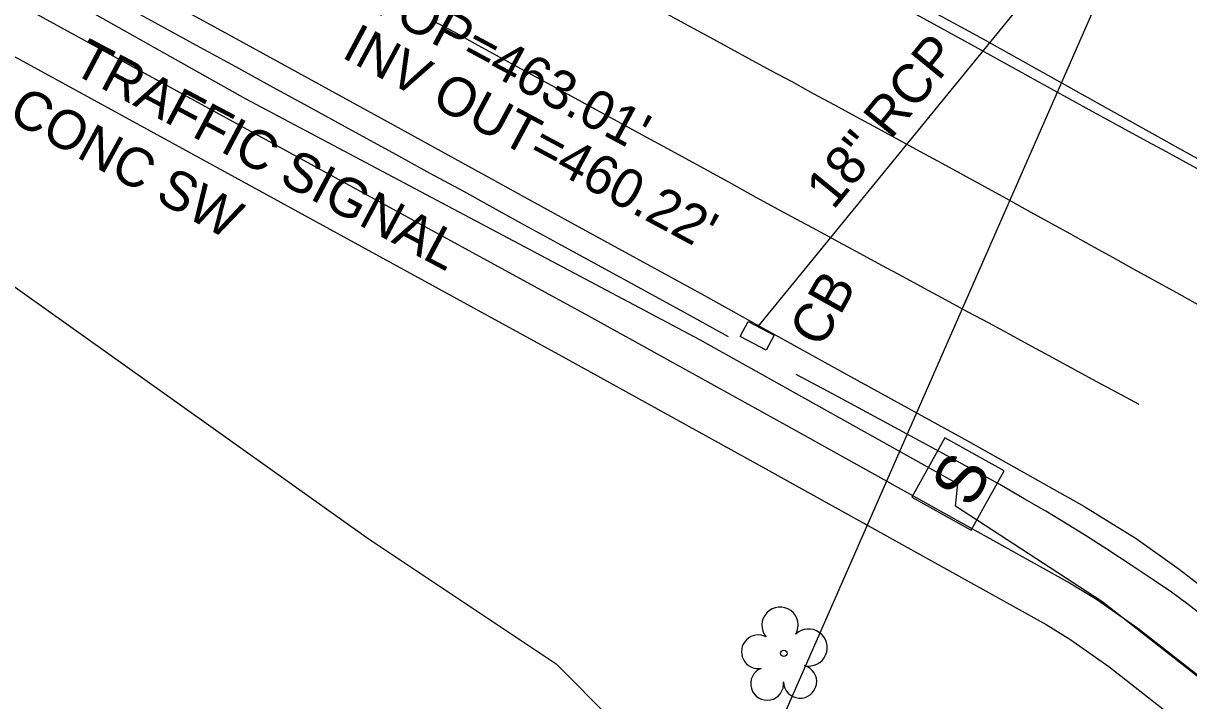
# Model space of a CAD drawing. Extents: x 2074109 to 2077820, y 741079 to 746031.
# Drawn here: x 2074923.4 to 2075042.9, y 743570.1 to 743639.5 of the extents above; entities that cross this region are included whole.
import ezdxf

# ---------------------------------------------------------------- set-up
doc = ezdxf.new("R2010")
doc.units = 0
for name, color, linetype in [('Exist Roads Curbs', 7, 'Continuous'), ('Exist Roads EOP', 7, 'Continuous'), ('Exist Roads EOP Other', 7, 'Continuous'), ('Exist Roads EOP Other Text', 7, 'Continuous'), ('Exist Roads EOT', 7, 'Continuous'), ('Exist Structure Minor Catch Basin', 7, 'Continuous'), ('Exist Structure Minor Catch Basin Text', 7, 'Continuous'), ('Exist Structure Minor Drop Inlet Top Elevation', 7, 'Continuous'), ('Exist Structure Minor Pipes RCP 18 Inch', 7, 'Continuous'), ('Exist Structure Minor Pipes RCP 18 Inch Invert', 7, 'Continuous'), ('Exist Structure Minor Pipes RCP 18 Inch Text', 7, 'Continuous'), ('Exist Structure Minor Pipes RCP 54 Inch', 7, 'Continuous'), ('Exist Utilities Other Traffic Signal Box CELL', 7, 'Continuous'), ('Exist Utilities Power UG Cable SUE LOS B', 7, 'Continuous'), ('Exist Utilities Power UG Cable SUE LOS B Text', 7, 'Continuous'), ('Exist Vegetation Tree CELL', 7, 'Continuous'), ('Exist Vegetation Woods Line', 7, 'Continuous')]:
    doc.layers.add(name, color=color, linetype=linetype)

msp = doc.modelspace()

# ---------------------------------------------------------------- linework, layer by layer
at = {"layer": 'Exist Roads Curbs'}
for points in [[(2074917.19, 743694.96), (2074926.95, 743689.34), (2074936.83, 743683.8), (2074947.07, 743678.19), (2074957.61, 743672.52), (2074968.41, 743666.75), (2074979.41, 743660.86), (2074990.43, 743654.92), (2075001.15, 743649.16), (2075011.47, 743643.59), (2075021.55, 743638.07), (2075031.64, 743632.44), (2075042.15, 743626.6), (2075053.19, 743620.49)], [(2074922.21, 743647.6), (2074925.14, 743646), (2074928.17, 743644.36), (2074931.3, 743642.65), (2074934.56, 743640.88), (2074937.96, 743639.03), (2074941.49, 743637.1), (2074945.16, 743635.09), (2074948.98, 743633), (2074952.95, 743630.83), (2074957.06, 743628.58), (2074961.25, 743626.29), (2074965.1, 743624.18), (2074968.53, 743622.31), (2074971.54, 743620.65), (2074974.39, 743619.09), (2074978.53, 743616.82), (2074984.23, 743613.7), (2074991.47, 743609.74), (2074995.67, 743607.44)], [(2075056.02, 743568.57), (2075054.3, 743570.23), (2075052.3, 743572.09), (2075050.06, 743574.09), (2075047.65, 743576.14), (2075045.13, 743578.18), (2075042.84, 743579.95), (2075041.13, 743581.22), (2075039.38, 743582.42), (2075037.01, 743584), (2075034.5, 743585.64), (2075032.31, 743587.04), (2075030.29, 743588.3), (2075028.25, 743589.51), (2075026.05, 743590.78), (2075023.53, 743592.24), (2075016.96, 743595.84), (2075006.96, 743601.23), (2075002.65, 743603.54)]]:
    msp.add_lwpolyline(points, dxfattribs=at)
at = {"layer": 'Exist Roads EOP'}
for points in [[(2074922.82, 743690.67), (2074926.1, 743688.81), (2074931.43, 743685.89), (2074937.13, 743682.79), (2074941.49, 743680.41), (2074946.08, 743677.9), (2074952.54, 743674.38), (2074960.81, 743669.87), (2074970.75, 743664.43), (2074980.82, 743658.94), (2074989.54, 743654.21), (2074997.67, 743649.82), (2075005.98, 743645.32), (2075013.05, 743641.48), (2075017.5, 743639.06), (2075021.29, 743636.97), (2075026.41, 743634.14), (2075032.37, 743630.86), (2075038.62, 743627.45), (2075040.22, 743626.58), (2075046.82, 743622.98)], [(2074913.35, 743655.38), (2074929.24, 743646.71), (2074944.83, 743638.18), (2074961.47, 743629.04), (2074979.24, 743619.29), (2074993.27, 743611.63), (2074999.52, 743608.13), (2075007.53, 743603.69), (2075020.31, 743596.69), (2075032.14, 743590.05), (2075037.51, 743586.73), (2075041.93, 743583.59), (2075046.53, 743580.01), (2075052.2, 743575.32), (2075057.95, 743570.11), (2075063.14, 743564.87)]]:
    msp.add_lwpolyline(points, dxfattribs=at)
at = {"layer": 'Exist Roads EOP Other'}
for points in [[(2074736.15, 743743.52), (2074745.36, 743738.39), (2074764.63, 743727.87), (2074783.88, 743717.41), (2074799.06, 743709.14), (2074820.47, 743697.56), (2074844.02, 743684.7), (2074871.78, 743669.61), (2074897.44, 743655.45), (2074932.64, 743636.17), (2074957.19, 743622.75), (2074981.37, 743609.53), (2075002.24, 743597.98), (2075030.68, 743582.18), (2075033.44, 743580.49), (2075037.68, 743577.54), (2075043.96, 743572.63), (2075050.45, 743567.5), (2075053.78, 743564.46), (2075055.44, 743566.25), (2075056.43, 743567.41)], [(2074733.88, 743739.15), (2074742.99, 743734.08), (2074762.28, 743723.55), (2074781.53, 743713.09), (2074796.71, 743704.81), (2074818.12, 743693.23), (2074841.67, 743680.38), (2074869.42, 743665.29), (2074895.07, 743651.14), (2074930.28, 743631.85), (2074954.82, 743618.43), (2074979, 743605.22), (2074999.86, 743593.68), (2075028.28, 743577.89), (2075030.72, 743576.39), (2075034.73, 743573.6), (2075040.92, 743568.76), (2075047.31, 743563.7), (2075054.69, 743557.36), (2075060.75, 743551.55), (2075061.79, 743551.62), (2075067.53, 743555.92)]]:
    msp.add_lwpolyline(points, dxfattribs=at)
at = {"layer": 'Exist Roads EOT'}
for points in [[(2074989.02, 743640.71), (2074991.22, 743639.52), (2074993.41, 743638.32), (2074995.61, 743637.13), (2074997.81, 743635.94), (2075000, 743634.74), (2075002.2, 743633.55), (2075004.39, 743632.35), (2075006.59, 743631.16), (2075008.79, 743629.97), (2075010.98, 743628.77), (2075013.18, 743627.59), (2075015.38, 743626.4), (2075017.58, 743625.21), (2075019.77, 743624.01), (2075021.96, 743622.8), (2075024.15, 743621.59), (2075026.34, 743620.38), (2075028.52, 743619.18), (2075030.71, 743617.97), (2075032.9, 743616.76), (2075035.09, 743615.55), (2075037.28, 743614.34), (2075039.46, 743613.13), (2075041.65, 743611.93), (2075043.84, 743610.72)], [(2075037.82, 743600.45), (2075035.62, 743601.64), (2075033.42, 743602.83), (2075031.23, 743604.02), (2075029.03, 743605.21), (2075026.83, 743606.4), (2075024.63, 743607.59), (2075022.43, 743608.78), (2075020.23, 743609.96), (2075018.03, 743611.15), (2075015.83, 743612.34), (2075013.64, 743613.53), (2075011.44, 743614.72), (2075009.24, 743615.91), (2075007.04, 743617.09), (2075004.84, 743618.28), (2075002.64, 743619.47), (2075000.44, 743620.66), (2074998.25, 743621.86), (2074996.06, 743623.06), (2074993.86, 743624.26), (2074991.67, 743625.46), (2074989.48, 743626.65), (2074987.28, 743627.85), (2074985.09, 743629.05), (2074982.89, 743630.25), (2074980.7, 743631.45), (2074978.51, 743632.65), (2074976.31, 743633.84), (2074974.12, 743635.04), (2074971.93, 743636.24), (2074969.73, 743637.44), (2074967.54, 743638.64), (2074965.34, 743639.83)]]:
    msp.add_lwpolyline(points, dxfattribs=at)
at = {"layer": 'Exist Structure Minor Catch Basin'}
msp.add_lwpolyline([(2074999.58, 743606.01), (2074996.9, 743607.44), (2074997.73, 743608.98), (2075000.41, 743607.55)], close=True, dxfattribs=at)
at = {"layer": 'Exist Structure Minor Pipes RCP 18 Inch'}
msp.add_line((2074998.76, 743608.45), (2075047.69, 743668.37), dxfattribs=at)
at = {"layer": 'Exist Structure Minor Pipes RCP 54 Inch'}
msp.add_line((2075074.8, 743735.81), (2074946.91, 743444.52), dxfattribs=at)
at = {"layer": 'Exist Utilities Other Traffic Signal Box CELL'}
msp.add_line((2075019.25, 743592.31), (2075019.25, 743592.31), dxfattribs=at)
msp.add_lwpolyline([(2075020.61, 743587.59), (2075023.97, 743593.67), (2075017.89, 743597.03), (2075014.53, 743590.95), (2075020.61, 743587.59)], dxfattribs=at)
at = {"layer": 'Exist Utilities Power UG Cable SUE LOS B'}
for points in [[(2074807.97, 743711.12), (2074807.03, 743709.66), (2074864.42, 743676.69), (2074899.54, 743658.03), (2074946.14, 743631.83), (2074992.75, 743607.11), (2075019.25, 743592.31)], [(2075056.41, 743555.92), (2075056.18, 743560.57), (2075053.43, 743565.07), (2075034.01, 743580.27), (2075019.01, 743590.04), (2075019.25, 743592.31)]]:
    msp.add_lwpolyline(points, dxfattribs=at)
at = {"layer": 'Exist Vegetation Tree CELL'}
msp.add_line((2075001.39, 743574.95), (2075001.39, 743574.95), dxfattribs=at)
msp.add_circle((2075001.39, 743574.95), 0.326, dxfattribs=at)
for centre, radius, start, end in [((2075001, 743577.83), 1.86, 330.1651, 219.7134), ((2075003.94, 743575.54), 1.9, 257.1011, 134.1999), ((2074998.78, 743575.11), 1.73, 62.6636, 279.3457), ((2074999.68, 743571.83), 1.69, 111.5671, 6.231), ((2075003.06, 743572.05), 1.7, 181.2822, 74.56)]:
    msp.add_arc(centre, radius, start, end, dxfattribs=at)
at = {"layer": 'Exist Vegetation Woods Line'}
msp.add_lwpolyline([(2074905.1, 743624.9), (2074958.77, 743586.73), (2074978.04, 743573.88), (2074995.23, 743556.58), (2075005.25, 743550.04), (2075020.25, 743543.63), (2075030.01, 743537.15), (2075038.16, 743526.18), (2075053.34, 743511.04), (2075063.92, 743504.02), (2075066.65, 743499.3), (2075067.63, 743486.43), (2075064.69, 743471.93), (2075068.31, 743459.01), (2075075.3, 743432.9), (2075075.94, 743409.67), (2075071.68, 743391.87), (2075067.29, 743377.76), (2075068.15, 743357.32)], dxfattribs=at)

# ---------------------------------------------------------------- texts
at = {"layer": 'Exist Roads EOP Other Text'}
msp.add_text('60" CONC SW', height=4, rotation=331.3247, dxfattribs=at).set_placement((2074913.49, 743634.2))
at = {"layer": 'Exist Structure Minor Catch Basin Text'}
msp.add_text('CB', height=4, rotation=60.742, dxfattribs=at).set_placement((2075005.26, 743606.12))
at = {"layer": 'Exist Structure Minor Drop Inlet Top Elevation'}
msp.add_text("TOP=463.01'", height=4, rotation=331.804, dxfattribs=at).set_placement((2074958.46, 743641.16))
at = {"layer": 'Exist Structure Minor Pipes RCP 18 Inch Invert'}
msp.add_text("INV OUT=460.22'", height=4, rotation=331.804, dxfattribs=at).set_placement((2074955.91, 743636.11))
at = {"layer": 'Exist Structure Minor Pipes RCP 18 Inch Text'}
msp.add_text('18" RCP', height=4, rotation=50.762, dxfattribs=at).set_placement((2075006.46, 743620.31))
at = {"layer": 'Exist Utilities Other Traffic Signal Box CELL'}
msp.add_text('S', height=5, rotation=61.1015, dxfattribs=at).set_placement((2075020.65, 743589.67))
at = {"layer": 'Exist Utilities Power UG Cable SUE LOS B Text'}
msp.add_text('TRAFFIC SIGNAL', height=4, rotation=332.0661, dxfattribs=at).set_placement((2074928.22, 743634.54))

doc.saveas('drawing.dxf')
